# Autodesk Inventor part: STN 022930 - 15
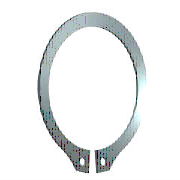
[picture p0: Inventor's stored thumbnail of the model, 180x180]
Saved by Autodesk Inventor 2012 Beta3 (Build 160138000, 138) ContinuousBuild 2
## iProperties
IsCustomPart: 0
Created: 2010-02
Part Number: STN 022930 - 15
Material: Steel, Mild
Description: Retaining rings for shaft
Document SubType Name: Modeling
Standard: STN 022930
Designer: Thom Tremblay
Standards Organization: STN
Language: en-US
Size Designation: 15
Categories: <MemberInstance><Categories><Category DisplayName="Shaft Parts" InternalName="7f7aeb1f-a693-4053-b835-cee3144e0d98" Mnemonic="SHFT"><Category DisplayName="Circl
Density: 7.86 g/cm^3
Author: Thom Tremblay
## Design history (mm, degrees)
node "WorkPlane1"
workplane "Work Plane2"
node "WorkPlane2"
node "Sketch1"
node "WorkPoint1"
node "WorkAxis1"
sketch "Sketch3"
  geometry: L1 (-0.85, -7.099)-(-0.85, -10.599) reference; L2 (-0.85, -10.599)-(-4.25, -10) reference; 1 further point
  dimensions: "d30" = 1.36 distance from line of L1 point (-2.21, -8.76) (= 0.8 x Diam5); "d32" = 1.575 distance from line of L2 point (-2.21, -8.76) (= 0.45 x ParA)
hole "Hole1" sketch "Sketch3" at (-2.21, -8.76) diameter "d33" = 1.7 (= Diam5); stored, may be unused: countersink angle "d37" = 60 deg, drill point angle "d39" = 118 deg; dims "d34" = 6, "d35" = 4, "d36" = 2, "d38" = 8
sketch "Sketch4"
  geometry: L1 (0.85, -10.599)-(0.85, -7.099) reference; L2 (4.25, -10)-(0.85, -10.599) reference; 1 further point
  dimensions: "d41" = 1.36 distance from line of L1 point (2.21, -8.76) (= 0.8 x Diam5); "d43" = 1.575 distance from line of L2 point (2.21, -8.76) (= 0.45 x ParA)
hole "Hole2" sketch "Sketch4" at (2.21, -8.76) diameter "d44" = 1.7 (= Diam5); stored, may be unused: countersink angle "d48" = 60 deg, drill point angle "d50" = 118 deg; dims "d45" = 6, "d46" = 4, "d47" = 2, "d49" = 8
fillet "Fillet1" dims "d51" = 2.55 (= 1.5 x Diam5)
body "Solid1"
sketch "Sketch2"
  geometry: L1 (4.25, -10)-(4.25, -7.227); L2 (0.85, -10.599)-(4.25, -10); L3 (0.85, -7.099)-(0.85, -10.599); L4 (-0.85, -7.099)-(-0.85, -10.599); L5 (-0.85, -10.599)-(-4.25, -10); L6 (-4.25, -10)-(-4.25, -7.227); A1 r 7.15 centre (0, 0) between (0.85, -7.099) and (-0.85, -7.099); A2 r 8.833 centre (0, 0.517) between (4.25, -7.227) and (-4.25, -7.227); 1 further point
  constraints: 12 end point, 4 point on circle, 4 vertical, 2 centre point
  dimensions: "d2" = 7.15 radius of A1 (= 0.5 x Diam2); "d4" = 8.83333 radius of A2 (= 0.166667 x ParA + 0.5 x Diam2 + 0.5 x b); "d6" = 0 horizontal distance of A2.centre A1.centre; "d8" = 0.85 horizontal distance of L3.start A1.centre (= 0.5 x Diam5); "d10" = 0.85 horizontal distance of L4.start A1.centre (= 0.5 x Diam5); "d12" = 3.5 distance of L4.start L4.end (= ParA); "d14" = 3.5 distance of L3.start L2.start (= ParA); "d16" = 80 deg angle of L2 L3; "d18" = 80 deg angle of L4 L5; "d20" = 3.4 horizontal distance of L4.start L6.end (= 2 x Diam5); "d22" = 3.4 horizontal distance of L1.start L3.start (= 2 x Diam5); "d24" = 0.51667 distance of A1.centre A2.centre (= -msp_r2 + 0.5 x Diam2 + b); "d52" = 0 distance of point (0, 0) A1.centre; "d53" = 0 distance of A1.centre point (0, 0)
extrude "Extrusion1" new body sketch "Sketch2" distance "d25" = 1 (= ParS); taper "d26" = 0 deg
other parameters: "Diam5" = 1.7 [user parameter; used in 9 equation terms], "ParA" = 3.5 [user parameter; used in 6 equation terms], "b" = 2.2 [user parameter; used in 3 equation terms], "ParS" = 1 [user parameter; used in 2 equation terms], "Diam2" = 14.3 [user parameter; used in 4 equation terms], "msp_r2" = 8.83333 (= 0.166667 x ParA + 0.5 x Diam2 + 0.5 x b) [user parameter; used in 1 equation term], "d0" = -1 (computed from ParS), "d1" = 14.3 (derived), "d3" = 0, "d5" = 0 (derived), "d7" = 1 (derived), "d9" = 1 (derived), "d11" = 4.8 (derived), "d13" = 4.8 (derived), "d15" = 80 deg (derived), "d17" = 80 deg (derived), "d19" = 4 (derived), "d21" = 4 (derived), "d23" = 0.95 (derived), "d27" = 0, "d28" = 0, "d29" = 1.6 (derived), "d31" = 2.16 (derived), "d40" = 1.6 (derived), "d42" = 2.16 (derived), "d55" = 0, "d56" = 0, "d57" = 0, "d58" = 0, "TEMPLATE" = 12.345 [user parameter]
